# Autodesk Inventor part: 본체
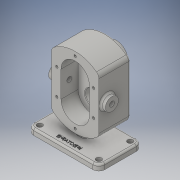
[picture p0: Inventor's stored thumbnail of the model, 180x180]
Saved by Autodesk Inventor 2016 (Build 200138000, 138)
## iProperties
Created: 2019-03
Part Number: 본체
Material: 일반
Document SubType Name: Modeling
Designer: Administrator
Density: 1 g/cm^3
Appearance: 기본값
Mass: 439.675 g
Surface Area: 719.247 cm^2
Volume: 439.675 cm^3
Author: Administrator
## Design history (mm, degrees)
sketch "스케치2"
  geometry: L1 (60, 36.5)-(-60, 36.5); L2 (-60, 36.5)-(-60, -36.5); L3 (-60, -36.5)-(60, -36.5); L4 (60, -36.5)-(60, 36.5); L5 (60, 36.5)-(-60, -36.5); L6 (-60, 36.5)-(60, -36.5); 1 further point
  constraints: 12 end point, 2 midpoint, 2 parallel, 1 horizontal, 1 perpendicular
  dimensions: "d4" = 120 distance of L2.end L3.end; "d5" = 73 distance of L1.end L2.end
extrude "돌출1" new body sketch "스케치2" distance "d6" = 10; taper "d7" = 0 deg
sketch "스케치4"
  geometry: L1 (60, 0)-(60, 78); L2 (20, 122.721)-(20, 33.279); L3 (100, 122.721)-(100, 33.279); A1 r 60 centre (60, 78) between (100, 122.721) and (20, 122.721); A2 r 60 centre (60, 78) between (20, 33.279) and (100, 33.279)
  constraints: 6 end point, 4 point on circle, 3 vertical, 2 centre point, 2 coincident, 1 other
  dimensions: "d8" = 78 distance of L1.start L1.end; "d9" = 80 distance between parallel lines of L3 L2; "d11" = 60 radius of A1; "d12" = 60 radius of A2
extrude "돌출2" join sketch "스케치4" distance "d13" = 53; taper "d14" = 0 deg
sketch "스케치5"
  geometry: L1 (60, -27.6)-(60, 165.6) reference; C1 r 19 at (60, 100); A1 r 60 centre (60, 78) between (100, 122.721) and (20, 122.721) reference; 1 further point
  constraints: 1 centre point, 1 point on line
  dimensions: "d15" = 38 diameter of C1; "d16" = 22 distance of A1.centre C1.centre
extrude "돌출3" join sketch "스케치5" distance "d17" = 17; taper "d18" = 0 deg
sketch "스케치6"
  geometry: L1 (-60, 56)-(-60, 100); L2 (-84, 56)-(-84, 100); L3 (-36, 100)-(-36, 56); A1 r 60 centre (-60, 78) between (-20, 122.721) and (-100, 122.721) reference; A2 r 24 centre (-60, 56) between (-84, 56) and (-36, 56); A3 r 24 centre (-60, 100) between (-36, 100) and (-84, 100); 1 further point
  constraints: 8 end point, 4 point on circle, 4 tangent, 2 centre point, 1 midpoint, 1 parallel, 1 vertical
  dimensions: "d20" = 24 radius of A3; "d21" = 44 distance of L1.start L1.end
extrude "돌출4" cut sketch "스케치6" distance "d22" = 29; taper "d23" = 0 deg
sketch "스케치7"
  geometry: L1 (-84, 56)-(-84, 100) reference; L2 (-36, 100)-(-36, 56) reference; C1 r 12.5 at (-60, 100); C2 r 12.5 at (-60, 56); A1 r 24 centre (-60, 56) between (-84, 56) and (-36, 56) reference; A2 r 24 centre (-60, 100) between (-36, 100) and (-84, 100) reference; 1 further point
  constraints: 2 centre point, 2 coincident
  dimensions: "d24" = 25 diameter of C1; "d25" = 25 diameter of C2
extrude "돌출5" cut sketch "스케치7" distance "d26" = 15; taper "d27" = 0 deg
sketch "스케치8"
  geometry: C1 r 19 at (0, 0) reference; C2 r 14 at (0, 0); 1 further point
  constraints: 1 centre point, 1 coincident
  dimensions: "d28" = 28 diameter of C2
extrude "돌출6" cut sketch "스케치8" distance "d29" = 7.3; taper "d30" = 0 deg
sketch "스케치9"
  geometry: C1 r 19 at (0, 0) reference; C2 r 8.5 at (0, 0); 1 further point
  constraints: 1 centre point, 1 coincident
  dimensions: "d31" = 17 diameter of C2
extrude "돌출7" cut sketch "스케치9" stored distance "d32" = 7.3; taper "d33" = 0 deg
sketch "스케치10"
  geometry: L1 (25, 6.5)-(10, 6.5); L2 (10, 6.5)-(10, -36.5); L3 (10, -36.5)-(25, -36.5); L4 (25, -36.5)-(25, 6.5); L5 (10, -36.5)-(10, 36.5) reference; L6 (0, -36.5)-(10, -36.5) reference; 1 further point
  constraints: 8 end point, 2 collinear, 2 parallel, 1 horizontal, 1 perpendicular
  dimensions: "d34" = 43 distance of L1.end L2.end; "d35" = 15 distance between parallel lines of L2 L4
extrude "돌출8" join sketch "스케치10" stored distance "d36" = 12; taper "d37" = 0 deg
sketch "스케치11"
  geometry: L1 (-39, 107.872)-(-39, 18.143); L2 (-53, 104.721)-(-53, 89.443) reference; L3 (-62.692, 44.721)-(12.571, 44.721); C1 r 11 at (-39, 44.721); 1 further point
  constraints: 4 end point, 2 point on line, 1 centre point, 1 horizontal, 1 vertical
  dimensions: "d39" = 14 distance between parallel lines of L2 L1; "d40" = 78 distance from line of point (-36.5, -33.279) L3; "d41" = 22 diameter of C1
extrude "돌출9" join sketch "스케치11" distance "d42" = 8; taper "d43" = 0 deg
sketch "스케치12"
  geometry: L1 (-60, 56)-(-60, 100); L2 (-29, 56)-(-29, 100); L3 (-91, 100)-(-91, 56); L4 (-60, 100)-(-60, 131); L5 (-60, 56)-(-60, 25); L6 (-91, 56)-(-29, 56); L7 (-91, 100)-(-29, 100); A1 r 60 centre (-60, 78) between (-20, 122.721) and (-100, 122.721) reference; A2 r 31 centre (-60, 56) between (-91, 56) and (-29, 56); A3 r 31 centre (-60, 100) between (-29, 100) and (-91, 100); 1 further point
  constraints: 16 end point, 6 point on circle, 4 tangent, 3 vertical, 2 centre point, 2 horizontal, 1 midpoint, 1 parallel
  dimensions: "d44" = 44 distance of L1.start L1.end; "d45" = 31 radius of A3
hole "구멍1" sketch "스케치12" at (-60, 131), (-29, 100), (-91, 100), (-91, 56), (-29, 56), (-60, 25) diameter "d46" = 4.134; stored, may be unused: countersink angle "d50" = 90 deg, drill point angle "d52" = 120 deg; dims "d47" = 10, "d48" = 4, "d49" = 2, "d51" = 12
fillet "모깎기1" dims "d53" = 10
sketch "스케치14"
  geometry: L1 (50, 36.5)-(-50, 36.5) reference; L2 (60, -26.5)-(60, 26.5) reference; L3 (-50, -36.5)-(50, -36.5) reference; L4 (-60, 26.5)-(-60, -26.5) reference; C1 r 4.5 at (-50, 26.5); C2 r 4.5 at (50, 26.5); C3 r 4.5 at (-50, -26.5); C4 r 4.5 at (50, -26.5); A1 r 10 centre (-50, 26.5) between (-50, 36.5) and (-60, 26.5) reference; A2 r 10 centre (50, 26.5) between (60, 26.5) and (50, 36.5) reference; A3 r 10 centre (50, -26.5) between (50, -36.5) and (60, -26.5) reference; A4 r 10 centre (-50, -26.5) between (-60, -26.5) and (-50, -36.5) reference; 1 further point
  constraints: 4 centre point, 4 coincident, 3 equal radius
  dimensions: "d54" = 9 diameter of C1
extrude "돌출10" cut sketch "스케치14" stored distance "d55" = 8; taper "d56" = 0 deg
sketch "스케치15"
  geometry: C1 r 11 at (0, 0) reference; 1 further point
hole "구멍2" sketch "스케치15" at (0, 0) diameter "d57" = 8.376; stored, may be unused: countersink angle "d61" = 90 deg, drill point angle "d63" = 120 deg; dims "d58" = 20, "d59" = 4, "d60" = 2, "d62" = 27.3
fillet "모깎기2" dims "d67" = 0.5
chamfer "모따기2" distance "d68" = 1; stored, may be unused: second distance "d69" = 2, angle "d70" = 30 deg
fillet "모깎기3" dims "d71" = 10
fillet "모깎기4" dims "d72" = 3
fillet "모깎기5" dims "d73" = 3
fillet "모깎기6" dims "d74" = 3
chamfer "모따기3" distance "d79" = 0.7; stored, may be unused: second distance "d80" = 2, angle "d81" = 30 deg
sketch "스케치16"
  geometry: L1 (-60, 26.5)-(-60, -26.5) reference; L2 (-50, -36.5)-(50, -36.5) reference; 2 further points
  constraints: 1 other
  dimensions: "d75" = 60 distance from line of L1 point (0, -26.5); "d76" = 10 distance from line of L2 point (0, -26.5)
feature "엠보싱1" sketch "스케치16" dims "d4" = 120, "d5" = 73, "d15" = 38, "d16" = 22, "d77" = 0.5, "d78" = 0
node "솔리드1"
mirror "대칭1"
node "투영된 루프1"
node "투영된 루프2"
